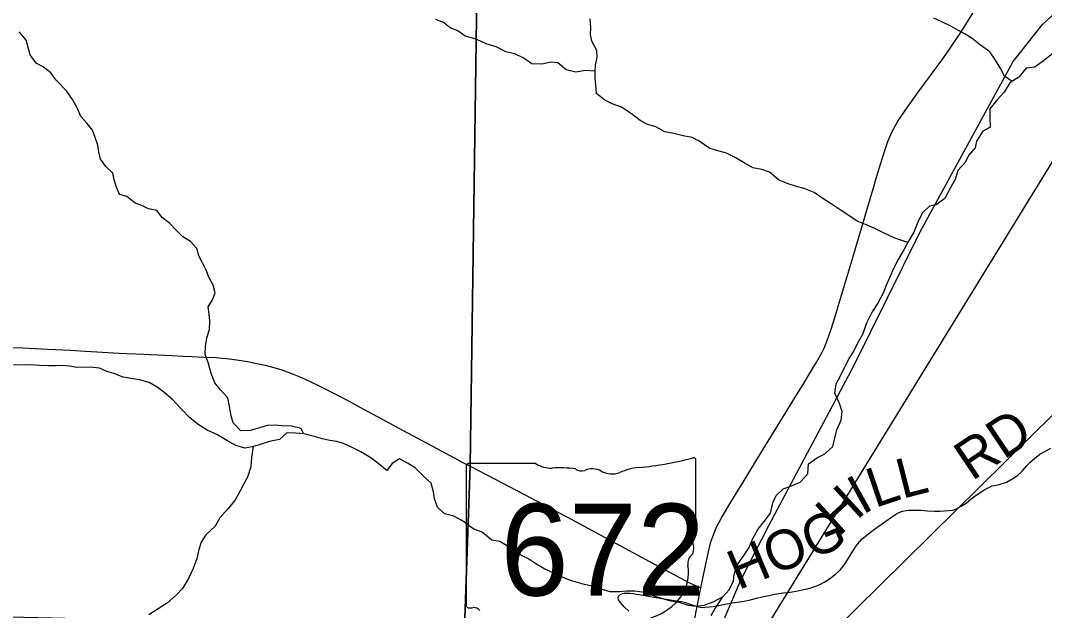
# Model space of a CAD drawing. Extents: x 0 to 34, y 0 to 22.
# Drawn here: x 4.145 to 5.615, y 18.153 to 19 of the extents above; entities that cross this region are included whole.
import ezdxf

# ---------------------------------------------------------------- set-up
doc = ezdxf.new("R2010")
doc.units = 0
for name, color, linetype in [('GM_X_Corporation', 7, 'Continuous'), ('GM_X_Minor_River', 7, 'Continuous'), ('GM_X_Rail_Line', 7, 'Continuous'), ('GM_X_State_Location', 7, 'Continuous'), ('GM_X_State_Route', 7, 'Continuous'), ('GM_X_State_Shield', 7, 'Continuous'), ('GM_X_Township_Road', 7, 'Continuous'), ('GM_X_Township_Road_Text', 7, 'Continuous'), ('SH_Text', 7, 'Continuous')]:
    doc.layers.add(name, color=color, linetype=linetype)

msp = doc.modelspace()

# ---------------------------------------------------------------- linework, layer by layer
at = {"layer": 'GM_X_Corporation'}
for points in [[(4.7823, 18.128), (4.7905, 18.3604), (4.8074, 19.5455), (4.8169, 20.042), (4.8194, 20.1261), (5.11, 20.116), (6.0551, 20.0845), (6.4901, 20.0752), (6.7204, 20.0659), (7.3691, 20.0515), (7.3901, 20.051), (7.814, 20.0425), (8.4311, 20.028), (8.4311, 21.3734), (1.6311, 21.3734)], [(4.0508, 18.1454), (4.7823, 18.128), (4.7905, 18.3604), (4.8074, 19.5455), (4.8169, 20.042), (4.8194, 20.1261), (5.11, 20.116), (6.0551, 20.0845), (6.4901, 20.0752), (6.7204, 20.0659), (7.3691, 20.0515), (7.3901, 20.051), (7.814, 20.0425), (8.4311, 20.028), (8.4311, 21.3734), (2.7987, 21.3734)], [(8.4311, 14.5734), (8.4311, 20.028), (7.814, 20.0425), (7.3901, 20.051), (7.3691, 20.0515), (6.7204, 20.0659), (6.4901, 20.0752), (6.0551, 20.0845), (5.11, 20.116), (4.8194, 20.1261), (4.8169, 20.042), (4.8074, 19.5455), (4.7905, 18.3604), (4.7823, 18.128)], [(8.4311, 16.0029), (8.4311, 20.028), (7.814, 20.0425), (7.3901, 20.051), (7.3691, 20.0515), (6.7204, 20.0659), (6.4901, 20.0752), (6.0551, 20.0845), (5.11, 20.116), (4.8194, 20.1261), (4.8169, 20.042), (4.8074, 19.5455), (4.7905, 18.3604), (4.7823, 18.128)]]:
    msp.add_lwpolyline(points, dxfattribs=at)
at = {"layer": 'GM_X_Minor_River'}
for points in [[(4.7944, 18.9749), (4.7833, 18.9776), (4.773, 18.9851), (4.762, 18.9895), (4.7525, 18.997), (4.7415, 19.0014)], [(5.4188, 18.6815), (5.4001, 18.6876), (5.385, 18.6948), (5.3714, 18.7016), (5.3581, 18.7073), (5.346, 18.7119), (5.334, 18.7199), (5.323, 18.7271), (5.309, 18.7369), (5.2954, 18.7453), (5.2845, 18.7533), (5.2701, 18.759), (5.2592, 18.7616), (5.2456, 18.7658), (5.2331, 18.7715), (5.2203, 18.7825), (5.2093, 18.786), (5.1961, 18.7886), (5.184, 18.7959), (5.1708, 18.8035), (5.1587, 18.8095), (5.1447, 18.8133), (5.1345, 18.8164), (5.1194, 18.827), (5.1092, 18.832), (5.0963, 18.8343), (5.0831, 18.8377), (5.0699, 18.84), (5.057, 18.8472), (5.0442, 18.8514), (5.0344, 18.8567), (5.0223, 18.8662), (5.0079, 18.8757), (4.9943, 18.8806), (4.9837, 18.8856), (4.972, 18.8951), (4.9709, 18.9076), (4.9698, 18.9171), (4.9698, 18.9269), (4.9706, 18.9364), (4.9729, 18.947), (4.9722, 18.9568), (4.965, 18.9705), (4.9635, 18.98), (4.9639, 18.9895), (4.9628, 19.0027)], [(5.5685, 18.9125), (5.5578, 18.9201), (5.5514, 18.9322), (5.5446, 18.9432), (5.5363, 18.955), (5.5231, 18.9649), (5.511, 18.9744), (5.5012, 18.9804), (5.4914, 18.9858), (5.4816, 18.9915), (5.4668, 18.9987), (5.4559, 19.0036)], [(4.4164, 18.5562), (4.4168, 18.5684), (4.4159, 18.5783), (4.4143, 18.5888), (4.4206, 18.5991), (4.4247, 18.609), (4.4216, 18.62), (4.4158, 18.6305), (4.4116, 18.6415), (4.4062, 18.652), (4.4012, 18.6622), (4.3981, 18.6728), (4.3893, 18.6829), (4.3783, 18.6896), (4.3684, 18.699), (4.3588, 18.7091), (4.3482, 18.7173), (4.3409, 18.7271), (4.3288, 18.7296), (4.3193, 18.7345), (4.3098, 18.7378), (4.2976, 18.7475), (4.2874, 18.7504), (4.2828, 18.7606), (4.2797, 18.7712), (4.2777, 18.781), (4.2674, 18.7904), (4.2597, 18.8009), (4.2574, 18.8111), (4.2562, 18.8213), (4.2523, 18.8319), (4.2484, 18.8425), (4.2408, 18.8522), (4.2316, 18.8624), (4.2266, 18.8748), (4.2197, 18.8865), (4.2113, 18.8993), (4.1956, 18.915), (4.1884, 18.9248), (4.1781, 18.933), (4.1678, 18.939), (4.159, 18.9506), (4.1559, 18.9612), (4.1539, 18.9714), (4.1432, 18.9838)], [(4.9699, 18.9274), (4.9562, 18.9281), (4.9422, 18.9258), (4.9282, 18.9292), (4.9165, 18.9395), (4.9067, 18.9403), (4.8935, 18.9372), (4.8791, 18.938), (4.8674, 18.946), (4.8545, 18.9521), (4.8417, 18.9551), (4.8277, 18.9623), (4.8134, 18.9665), (4.8009, 18.9722), (4.7944, 18.9749)], [(5.6267, 18.9522), (5.6134, 18.942), (5.6013, 18.9329)], [(5.6013, 18.9329), (5.5885, 18.9318), (5.5782, 18.9186), (5.5654, 18.9106), (5.557, 18.897), (5.5464, 18.8856), (5.5366, 18.8731), (5.5365, 18.8599), (5.5369, 18.847), (5.5267, 18.8413), (5.5172, 18.8269), (5.5153, 18.8174), (5.5058, 18.8064), (5.5009, 18.7962), (5.4906, 18.7849), (5.4868, 18.7716), (5.4789, 18.7583), (5.472, 18.7447), (5.4595, 18.7356), (5.4497, 18.7334), (5.4395, 18.7235), (5.433, 18.7106), (5.4273, 18.6962), (5.4197, 18.6834), (5.4133, 18.6709), (5.4049, 18.6568), (5.3981, 18.644), (5.3932, 18.6315), (5.3871, 18.6186), (5.3833, 18.6087), (5.3757, 18.5943), (5.3677, 18.5818), (5.3604, 18.5673)], [(4.7838, 18.2785), (4.7959, 18.2701), (4.8084, 18.2653), (4.8217, 18.2543), (4.8331, 18.2524), (4.8425, 18.2464), (4.8524, 18.2389), (4.8649, 18.2317), (4.8748, 18.2268), (4.8846, 18.2204), (4.8979, 18.2125), (4.9142, 18.205), (4.9237, 18.2005), (4.9343, 18.1963), (4.9442, 18.1933), (4.954, 18.1907), (4.9684, 18.1877), (4.9813, 18.1828), (4.9912, 18.1802), (5.0048, 18.1803), (5.015, 18.1811), (5.0267, 18.1811), (5.0415, 18.1789), (5.0555, 18.1732), (5.0654, 18.1706), (5.0764, 18.1672), (5.09, 18.165), (5.1033, 18.1605), (5.115, 18.159), (5.1264, 18.1606), (5.1392, 18.1652), (5.1536, 18.1728), (5.1623, 18.1823), (5.1687, 18.1952), (5.1694, 18.2047), (5.1735, 18.2176), (5.1826, 18.2302), (5.1909, 18.2435), (5.1965, 18.256), (5.2033, 18.2689), (5.2124, 18.2807), (5.2218, 18.2928), (5.2252, 18.3073), (5.2297, 18.3179), (5.2399, 18.3274), (5.2508, 18.3312), (5.2641, 18.337), (5.2754, 18.3491), (5.2761, 18.3632), (5.2893, 18.3723), (5.2995, 18.3777), (5.3112, 18.3883), (5.3142, 18.4004), (5.3168, 18.4122), (5.3229, 18.4263), (5.3247, 18.4384), (5.3209, 18.4501), (5.314, 18.4649), (5.3159, 18.4785), (5.3215, 18.4888), (5.3283, 18.5025), (5.3347, 18.5146), (5.3407, 18.5245), (5.3471, 18.537), (5.3543, 18.5496), (5.3604, 18.5673)], [(4.5512, 18.4067), (4.5482, 18.4142), (4.5342, 18.4175), (4.5202, 18.4181), (4.5107, 18.4188), (4.4993, 18.4183), (4.4883, 18.4152), (4.4747, 18.4113), (4.4614, 18.4108), (4.4504, 18.4225), (4.4473, 18.4323), (4.4453, 18.446), (4.4429, 18.4581), (4.4322, 18.4698), (4.4242, 18.4796), (4.4188, 18.4932), (4.4149, 18.5076), (4.4102, 18.5208), (4.4105, 18.5318), (4.4127, 18.5444), (4.4164, 18.5562)], [(4.7838, 18.2785), (4.7778, 18.2824), (4.7671, 18.2881), (4.7538, 18.2914), (4.7435, 18.3012), (4.7396, 18.3133), (4.7377, 18.3231), (4.7346, 18.3356), (4.7231, 18.3461), (4.7117, 18.3578), (4.7006, 18.3642), (4.6892, 18.3705), (4.6786, 18.364), (4.6711, 18.3537), (4.6578, 18.3646), (4.6482, 18.3721), (4.6334, 18.3807), (4.6212, 18.3871), (4.6098, 18.3923), (4.5992, 18.3956), (4.5889, 18.3971), (4.5787, 18.3992), (4.5654, 18.4033), (4.5521, 18.4066), (4.5396, 18.4077), (4.5274, 18.4079), (4.5169, 18.3984), (4.5025, 18.3956), (4.4877, 18.3909), (4.4775, 18.3878), (4.4673, 18.3858), (4.454, 18.3899), (4.4411, 18.397), (4.4281, 18.4052), (4.4129, 18.412), (4.4003, 18.4198), (4.3881, 18.4296), (4.3763, 18.442), (4.3637, 18.4552), (4.3507, 18.4665), (4.3412, 18.4736), (4.3298, 18.48), (4.3157, 18.484), (4.3062, 18.4855), (4.2926, 18.488), (4.2789, 18.4932), (4.269, 18.4962), (4.2587, 18.5006), (4.2451, 18.5021), (4.2254, 18.5019), (4.2159, 18.5037), (4.2056, 18.5048), (4.1954, 18.5043), (4.1852, 18.5042), (4.1727, 18.5045), (4.1579, 18.5055), (4.1351, 18.5053)], [(4.4793, 18.3883), (4.4769, 18.3726), (4.4758, 18.3593), (4.471, 18.3441), (4.4658, 18.3346), (4.4598, 18.3239), (4.4527, 18.3106), (4.4429, 18.2987), (4.4313, 18.2857), (4.4245, 18.2739), (4.4113, 18.2613), (4.4046, 18.251), (4.4009, 18.2403), (4.3983, 18.2274), (4.3931, 18.2133), (4.3864, 18.1989), (4.3774, 18.1844), (4.3687, 18.1748), (4.3559, 18.1637), (4.3427, 18.1553), (4.3291, 18.1468)], [(5.1526, 18.1723), (5.1427, 18.1572), (5.1359, 18.1451)]]:
    msp.add_lwpolyline(points, dxfattribs=at)
at = {"layer": 'GM_X_Rail_Line'}
msp.add_lwpolyline([(5.1451, 18.1171), (5.1789, 18.1962), (5.2191, 18.2747), (5.3419, 18.505), (5.4365, 18.6966), (5.5699, 18.941), (5.612, 18.9944), (5.6684, 19.0468), (5.7239, 19.094), (5.7833, 19.1322), (5.9037, 19.1938), (6.0328, 19.261), (6.0812, 19.2894), (6.1283, 19.3307), (6.1601, 19.3803), (6.1751, 19.4374), (6.1878, 19.5161), (6.2911, 20.0794)], dxfattribs=at)
at = {"layer": 'GM_X_State_Route'}
msp.add_line((5.1165, 18.1584), (5.1218, 18.1855), dxfattribs=at)
for points in [[(5.3703, 18.763), (5.3726, 18.7705), (5.3794, 18.7939), (5.3858, 18.8135), (5.39, 18.8262), (5.3957, 18.8398), (5.4045, 18.8555), (5.4181, 18.8758), (5.4335, 18.8972), (5.4689, 18.9449), (5.495, 18.9828), (5.517, 19.0181), (5.5496, 19.0692), (5.5613, 19.0877), (5.5751, 19.1092), (5.5997, 19.148), (5.6076, 19.1596), (5.6113, 19.1649), (5.6154, 19.1703)], [(5.3536, 18.7067), (5.3598, 18.7276), (5.3703, 18.763)], [(5.1218, 18.1855), (5.1293, 18.2218), (5.1334, 18.2412), (5.1362, 18.2512), (5.1391, 18.2593), (5.1436, 18.2716), (5.1514, 18.2859), (5.1662, 18.3106), (5.1878, 18.3456), (5.203, 18.3709), (5.2429, 18.4359), (5.2703, 18.4806), (5.2877, 18.5093), (5.2958, 18.5237), (5.2987, 18.5296), (5.3017, 18.5366), (5.3075, 18.5526), (5.3131, 18.5704), (5.3237, 18.6056), (5.3359, 18.6466), (5.3536, 18.7067)], [(4.1332, 18.5304), (4.1482, 18.53), (4.1662, 18.5291), (4.1842, 18.5281), (4.1953, 18.5275), (4.217, 18.5266), (4.2382, 18.5254), (4.263, 18.5239), (4.2865, 18.5224), (4.2977, 18.5219), (4.3219, 18.5211), (4.3628, 18.5189), (4.3784, 18.5182), (4.3914, 18.5176), (4.4081, 18.5167), (4.4261, 18.5159), (4.4348, 18.5152), (4.4447, 18.5141), (4.4558, 18.5127), (4.4711, 18.5103), (4.4821, 18.5082), (4.4961, 18.505), (4.5087, 18.5017), (4.5201, 18.4983), (4.5277, 18.4957), (4.5365, 18.4923), (4.5485, 18.4874), (4.5611, 18.4818), (4.5739, 18.4755), (4.6009, 18.4616), (4.6157, 18.4537), (4.6376, 18.4419), (4.6578, 18.431), (4.6945, 18.4114), (4.7428, 18.3856), (4.7799, 18.3655), (4.7907, 18.3599)], [(4.7907, 18.3599), (4.8257, 18.342), (4.8765, 18.3153), (4.9365, 18.2833), (4.9887, 18.2551), (5.0541, 18.2197), (5.0911, 18.2001), (5.1065, 18.1922), (5.1218, 18.1855)], [(5.0884, 18.0194), (5.1042, 18.0973), (5.1099, 18.1258), (5.112, 18.1363), (5.1165, 18.1584)]]:
    msp.add_lwpolyline(points, dxfattribs=at)
at = {"layer": 'GM_X_State_Shield'}
for p, q in [((4.7849, 18.3602), (4.7849, 18.1601)), ((4.8846, 18.3637), (4.7881, 18.3637)), ((5.1144, 18.2639), (5.1144, 18.3686)), ((5.1144, 18.264), (5.1144, 18.2639))]:
    msp.add_line(p, q, dxfattribs=at)
for centre, major_axis, start_param, end_param in [((4.7886, 18.3606), (0.00382, 0), 1.712693, 3.28349), ((4.9076, 18.3869), (0.037, 0), 4.042523, 4.731795), ((4.997, 18.6365), (0.3495, 0), 4.814394, 5.042369), ((5.1108, 18.3691), (0.00367, 0), 6.141152, 7.989035), ((4.9199, 18.2513), (0.133, 0), 1.404758, 1.657858), ((4.9501, 18.3617), (0.0107, 0), 3.836095, 5.185415), ((4.9658, 18.3385), (0.0222, 0), 0.950623, 2.079405), ((4.9944, 18.3703), (0.0267, 0), 4.081561, 5.145723), ((5.0416, 18.3025), (0.0703, 0), 1.699011, 2.107814), ((5.1136, 18.2562), (0.00568, 0), 1.883978, 3.671073), ((5.1105, 18.2635), (0.00393, 0), 5.05454, 6.418171), ((5.0775, 18.243), (0.0341, 0), 5.934695, 6.695948), ((5.1276, 18.2201), (0.0248, 0), 2.387724, 3.262537), ((5.0166, 18.2068), (0.0874, 0), 5.101752, 6.440018), ((4.7887, 18.1597), (0.00385, 0), 3.00124, 4.508301), ((4.7893, 18.1801), (0.0294, 0), 4.665946, 4.897461), ((4.7953, 18.1485), (0.0106, 0), 0.519207, 1.627899)]:
    msp.add_ellipse(centre, major_axis=major_axis, ratio=0.8, start_param=start_param, end_param=end_param, dxfattribs=at)
at = {"layer": 'GM_X_Township_Road'}
for points in [[(5.1165, 18.1584), (5.1207, 18.1575), (5.124, 18.1573), (5.128, 18.1575), (5.1395, 18.1585), (5.1667, 18.1637), (5.1806, 18.1658), (5.1909, 18.1678), (5.2018, 18.1703), (5.2096, 18.1723), (5.217, 18.1738), (5.2278, 18.1761), (5.2337, 18.1772), (5.2404, 18.1781), (5.2498, 18.1793), (5.2607, 18.181), (5.2692, 18.1828), (5.2748, 18.184), (5.2794, 18.1852), (5.2855, 18.1874), (5.2923, 18.1901), (5.2988, 18.1935), (5.3037, 18.1965), (5.3084, 18.1996), (5.315, 18.2049), (5.3192, 18.2087), (5.3226, 18.2122), (5.3268, 18.2172), (5.3297, 18.2216), (5.3397, 18.2378), (5.3417, 18.2411), (5.3438, 18.244), (5.3465, 18.2481), (5.3497, 18.252), (5.3532, 18.2555), (5.3574, 18.259), (5.3653, 18.2653), (5.371, 18.2697), (5.3939, 18.2859), (5.4038, 18.2926), (5.4073, 18.2942), (5.4113, 18.2956), (5.4162, 18.2963), (5.42, 18.2967), (5.4243, 18.2969), (5.4312, 18.297), (5.4377, 18.2968), (5.447, 18.2961), (5.4569, 18.2953), (5.4647, 18.2954), (5.4771, 18.2962), (5.4832, 18.297), (5.4878, 18.2982), (5.4953, 18.3024), (5.5024, 18.3069), (5.5099, 18.3131), (5.5182, 18.3194), (5.5277, 18.3254), (5.5339, 18.329), (5.5399, 18.3317), (5.5501, 18.3337), (5.5603, 18.3372), (5.5694, 18.3422), (5.5763, 18.3467), (5.5827, 18.3528), (5.5892, 18.3601), (5.5943, 18.3656), (5.6004, 18.3713), (5.6081, 18.3773), (5.6243, 18.386)], [(5.0181, 18.152), (5.0117, 18.1583), (5.0058, 18.1649), (5.0036, 18.1681), (5.0029, 18.1708), (5.0035, 18.1732), (5.0053, 18.1755), (5.0092, 18.1772), (5.0114, 18.1778), (5.0146, 18.1779), (5.0199, 18.1776), (5.024, 18.1772), (5.0296, 18.1763), (5.0655, 18.1702), (5.0956, 18.1653), (5.0997, 18.1644), (5.1048, 18.1626), (5.1165, 18.1584)], [(5.0884, 18.0194), (5.1042, 18.0973), (5.1099, 18.1258), (5.112, 18.1363), (5.1165, 18.1584)]]:
    msp.add_lwpolyline(points, dxfattribs=at)
at = {"layer": 'SH_Text'}
msp.add_lwpolyline([(5.6652, 18.4716), (5.0586, 17.8726), (5.6652, 18.8602)], close=True, dxfattribs=at)

# ---------------------------------------------------------------- texts
at = {"layer": 'GM_X_State_Location'}
for s, p in [('s', (4.946, 18.2469)), ('r', (4.9459, 18.2469))]:
    msp.add_text(s, height=0.000189, dxfattribs=at).set_placement(p)
msp.add_text('672', height=0.000189, rotation=0, dxfattribs=at).set_placement((4.8791, 18.2331))
at = {"layer": 'GM_X_State_Shield'}
msp.add_text('672', height=0.13184, dxfattribs=at).set_placement((4.8339, 18.1742))
at = {"layer": 'GM_X_Township_Road_Text'}
for s, height, rotation, p in [('RD', 0.05682, 33.8254, (5.5108, 18.338)), ('L', 0.0568, 14.2857, (5.4107, 18.3131)), ('I', 0.0568, 28.9325, (5.3536, 18.2896)), ('L', 0.0568, 18.6843, (5.3716, 18.2998)), ('H', 0.0568, 42.3871, (5.3195, 18.2579)), ('HOG', 0.05682, 22.6437, (5.1755, 18.1818))]:
    msp.add_text(s, height=height, rotation=rotation, dxfattribs=at).set_placement(p)

doc.saveas('drawing.dxf')
